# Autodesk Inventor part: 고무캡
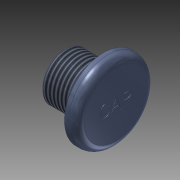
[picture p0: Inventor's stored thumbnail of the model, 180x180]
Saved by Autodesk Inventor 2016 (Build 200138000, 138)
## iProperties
Created: 2017-06
Part Number: 고무캡
Material: 고무
Document SubType Name: Modeling
Designer: mduedu
Density: 1 g/cm^3
Appearance: 고무 - 파란색 - 버전 1.1
Author: mduedu
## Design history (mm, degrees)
sketch "스케치1"
  geometry: L1 (0, 0)-(13, 0); L2 (13, 0)-(13, 10); L3 (13, 10)-(10, 10); L4 (0, 6)-(0, 0); L5 (0, 6)-(8, 6); L6 (8, 6)-(8, 8); L7 (8, 8)-(10, 8); L8 (10, 8)-(10, 10)
  constraints: 16 end point, 2 horizontal, 2 parallel, 2 perpendicular, 2 point on line, 1 vertical
  dimensions: "d0" = 20 diameter of L3 L1; "d2" = 12 diameter of L5 L1; "d6" = 5 distance between parallel lines of L2 L6; "d8" = 16 diameter of L7 L1; "d9" = 8 distance between parallel lines of L6 L4; "d32" = 2 distance of L6.end L7.end
revolve "회전1" sketch "스케치1" stored, may be unused: angle "d10" = 90 deg
hole "구멍1" diameter "d22" = 5; stored, may be unused: countersink angle "d26" = 90 deg, drill point angle "d28" = 0 deg; dims "d23" = 6, "d24" = 4, "d25" = 2, "d27" = 6, "d30" = 10, "d31" = 10
chamfer "모따기1" distance "d13" = 0.5; stored, may be unused: second distance "d14" = 2, angle "d15" = 45 deg
fillet "모깎기3" dims "d29" = 1
fillet "모깎기2" dims "d17" = 2
sketch "스케치3"
  geometry: 2 further points
  constraints: 1 coincident, 1 other
feature "엠보싱1" sketch "스케치3" dims "d18" = 0.2, "d19" = 0, "d29" = 1
feature "스레드1" dims "d33" = 10, "d34" = 0
node "솔리드1"
